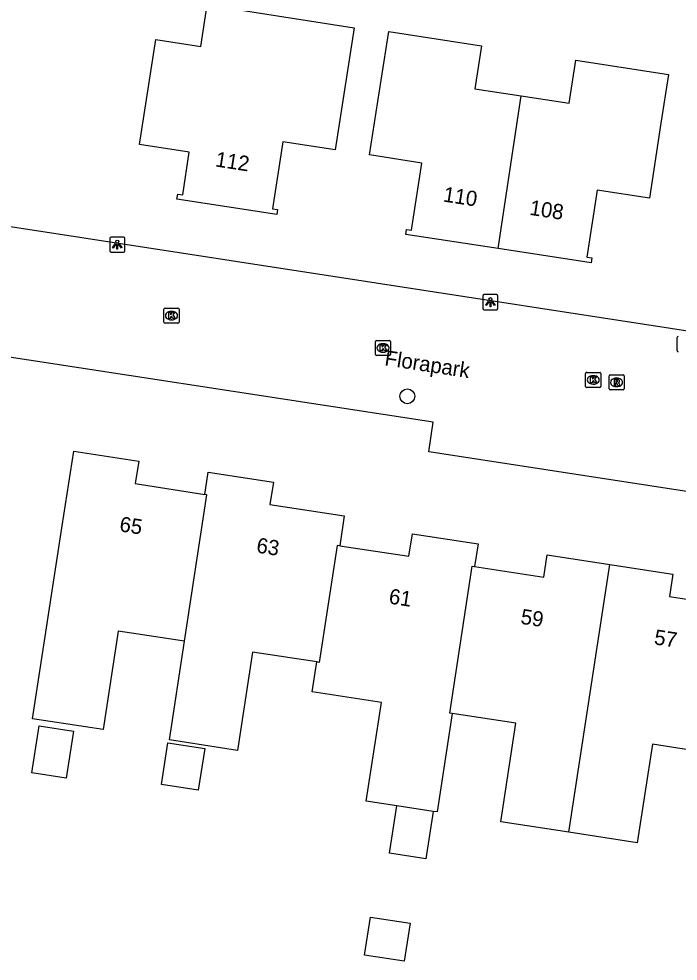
# Model space of a CAD drawing. Extents: x 161486 to 162249, y 379484 to 380829.
# Drawn here: x 161831.1 to 161874.7, y 380679.4 to 380741.6 of the extents above; entities that cross this region are included whole.
import ezdxf

# ---------------------------------------------------------------- set-up
doc = ezdxf.new("R2010")
doc.units = 0
for name, color, linetype in [('IMGEO_Boom', 7, 'Continuous'), ('IMGEO_Brandkraan', 7, 'Continuous'), ('IMGEO_Kolk', 7, 'Continuous'), ('IMGEO_Lichtpunt', 7, 'Continuous'), ('IMGEO_Openbare_ruimte_label', 7, 'Continuous'), ('IMGEO_Pand', 7, 'Continuous'), ('IMGEO_Pand_nummerreeks', 7, 'Continuous'), ('IMGEO_Rijbaan_lokaal_open', 7, 'Continuous'), ('IMGEO_Rioolput', 7, 'Continuous')]:
    doc.layers.add(name, color=color, linetype=linetype)

msp = doc.modelspace()

# ---------------------------------------------------------------- linework, layer by layer
at = {"layer": 'IMGEO_Boom'}
msp.add_circle((161856.794, 380716.676), 0.489, dxfattribs=at)
at = {"layer": 'IMGEO_Brandkraan'}
msp.add_line((161874.599, 380719.698), (161874.599, 380720.55), dxfattribs=at)
msp.add_lwpolyline([(161874.599, 380719.698), (161874.599, 380720.55)], dxfattribs=at)
for centre, start, end in [((161874.676, 380720.548), 91.55205, 178.44795), ((161874.676, 380720.548), 91.55205, 178.44795), ((161874.676, 380719.7), 181.55205, 268.44795), ((161874.676, 380719.7), 181.55205, 268.44795)]:
    msp.add_arc(centre, 0.0765, start, end, dxfattribs=at)
at = {"layer": 'IMGEO_Kolk'}
for p, q in [((161840.723, 380721.58), (161840.723, 380722.432)), ((161840.798, 380722.506), (161841.65, 380722.506)), ((161841.724, 380722.432), (161841.724, 380721.58)), ((161841.234, 380721.726), (161841.209, 380721.726)), ((161841.211, 380722.286), (161841.236, 380722.286)), ((161841.65, 380721.506), (161840.798, 380721.506)), ((161854.687, 380719.443), (161854.687, 380720.295)), ((161854.762, 380720.369), (161855.614, 380720.369)), ((161855.175, 380720.149), (161855.2, 380720.149)), ((161855.688, 380720.295), (161855.688, 380719.443)), ((161855.614, 380719.369), (161854.762, 380719.369)), ((161855.198, 380719.589), (161855.173, 380719.589)), ((161868.567, 380717.333), (161868.567, 380718.185)), ((161868.642, 380718.259), (161869.494, 380718.259)), ((161869.055, 380718.039), (161869.08, 380718.039)), ((161869.568, 380718.185), (161869.568, 380717.333)), ((161869.078, 380717.479), (161869.053, 380717.479)), ((161869.494, 380717.259), (161868.642, 380717.259))]:
    msp.add_line(p, q, dxfattribs=at)
for points in [[(161840.723, 380721.58), (161840.723, 380722.432)], [(161840.798, 380722.506), (161841.65, 380722.506)], [(161841.724, 380722.432), (161841.724, 380721.58)], [(161841.044, 380722.206), (161841.167, 380722.206), (161841.167, 380722.055), (161841.297, 380722.206), (161841.461, 380722.206), (161841.315, 380722.055), (161841.468, 380721.806), (161841.316, 380721.806), (161841.231, 380721.97), (161841.167, 380721.903), (161841.167, 380721.806), (161841.044, 380721.806), (161841.044, 380722.206)], [(161841.65, 380721.506), (161840.798, 380721.506)], [(161854.687, 380719.443), (161854.687, 380720.295)], [(161854.762, 380720.369), (161855.614, 380720.369)], [(161855.008, 380720.069), (161855.131, 380720.069), (161855.131, 380719.918), (161855.261, 380720.069), (161855.425, 380720.069), (161855.279, 380719.918), (161855.432, 380719.669), (161855.28, 380719.669), (161855.195, 380719.833), (161855.131, 380719.766), (161855.131, 380719.669), (161855.008, 380719.669), (161855.008, 380720.069)], [(161855.688, 380720.295), (161855.688, 380719.443)], [(161855.614, 380719.369), (161854.762, 380719.369)], [(161868.567, 380717.333), (161868.567, 380718.185)], [(161868.642, 380718.259), (161869.494, 380718.259)], [(161869.568, 380718.185), (161869.568, 380717.333)], [(161868.888, 380717.959), (161869.011, 380717.959), (161869.011, 380717.808), (161869.141, 380717.959), (161869.305, 380717.959), (161869.159, 380717.808), (161869.312, 380717.559), (161869.16, 380717.559), (161869.075, 380717.723), (161869.011, 380717.656), (161869.011, 380717.559), (161868.888, 380717.559), (161868.888, 380717.959)], [(161869.494, 380717.259), (161868.642, 380717.259)]]:
    msp.add_lwpolyline(points, dxfattribs=at)
for centre, start, end in [((161840.8, 380722.43), 91.55205, 178.44795), ((161840.8, 380722.43), 91.55205, 178.44795), ((161841.648, 380722.43), 1.55205, 88.44795), ((161841.648, 380722.43), 1.55205, 88.44795), ((161840.8, 380721.582), 181.55205, 268.44795), ((161840.8, 380721.582), 181.55205, 268.44795), ((161841.648, 380721.582), 271.55205, 358.44795), ((161841.648, 380721.582), 271.55205, 358.44795), ((161854.764, 380720.293), 91.55205, 178.44795), ((161854.764, 380720.293), 91.55205, 178.44795), ((161855.612, 380720.293), 1.55205, 88.44795), ((161855.612, 380720.293), 1.55205, 88.44795), ((161854.764, 380719.445), 181.55205, 268.44795), ((161854.764, 380719.445), 181.55205, 268.44795), ((161855.612, 380719.445), 271.55205, 358.44795), ((161855.612, 380719.445), 271.55205, 358.44795), ((161868.644, 380718.183), 91.55205, 178.44795), ((161868.644, 380718.183), 91.55205, 178.44795), ((161869.492, 380718.183), 1.55205, 88.44795), ((161869.492, 380718.183), 1.55205, 88.44795), ((161868.644, 380717.335), 181.55205, 268.44795), ((161868.644, 380717.335), 181.55205, 268.44795), ((161869.492, 380717.335), 271.55205, 358.44795), ((161869.492, 380717.335), 271.55205, 358.44795)]:
    msp.add_arc(centre, 0.0765, start, end, dxfattribs=at)
for centre, major_axis, ratio, start_param, end_param in [((161841.21, 380722.006), (-0.387, 0.002), 0.722429, 4.712389, 7.853982), ((161841.235, 380722.006), (-0.39, 0.002), 0.717154, 1.570796, 4.712389), ((161855.174, 380719.869), (-0.387, 0.002), 0.722429, 4.712389, 7.853982), ((161855.199, 380719.869), (-0.39, 0.002), 0.717154, 1.570796, 4.712389), ((161869.054, 380717.759), (-0.387, 0.002), 0.722429, 4.712389, 7.853982), ((161869.079, 380717.759), (-0.39, 0.002), 0.717154, 1.570796, 4.712389)]:
    msp.add_ellipse(centre, major_axis=major_axis, ratio=ratio, start_param=start_param, end_param=end_param, dxfattribs=at)
at = {"layer": 'IMGEO_Lichtpunt'}
for p, q in [((161837.141, 380727.096), (161837.141, 380726.289)), ((161837.141, 380727.096), (161837.141, 380726.289)), ((161838.043, 380727.191), (161837.235, 380727.191)), ((161838.043, 380727.191), (161837.235, 380727.191)), ((161838.137, 380726.289), (161838.137, 380727.096)), ((161838.137, 380726.289), (161838.137, 380727.096)), ((161837.235, 380726.195), (161838.043, 380726.195)), ((161837.235, 380726.195), (161838.043, 380726.195)), ((161861.781, 380723.296), (161861.781, 380722.489)), ((161861.781, 380723.296), (161861.781, 380722.489)), ((161862.683, 380723.391), (161861.875, 380723.391)), ((161862.683, 380723.391), (161861.875, 380723.391)), ((161862.777, 380722.489), (161862.777, 380723.296)), ((161862.777, 380722.489), (161862.777, 380723.296)), ((161861.875, 380722.395), (161862.683, 380722.395)), ((161861.875, 380722.395), (161862.683, 380722.395))]:
    msp.add_line(p, q, dxfattribs=at)
for points in [[(161837.515, 380726.76), (161837.554, 380726.732), (161837.366, 380726.47), (161837.328, 380726.497), (161837.515, 380726.76)], [(161837.617, 380726.712), (161837.664, 380726.712), (161837.664, 380726.39), (161837.617, 380726.39), (161837.617, 380726.712)], [(161837.727, 380726.732), (161837.765, 380726.759), (161837.952, 380726.497), (161837.913, 380726.469), (161837.727, 380726.732)], [(161862.155, 380722.96), (161862.194, 380722.932), (161862.006, 380722.67), (161861.968, 380722.697), (161862.155, 380722.96)], [(161862.257, 380722.912), (161862.304, 380722.912), (161862.304, 380722.59), (161862.257, 380722.59), (161862.257, 380722.912)], [(161862.367, 380722.932), (161862.405, 380722.959), (161862.592, 380722.697), (161862.553, 380722.669), (161862.367, 380722.932)]]:
    msp.add_lwpolyline(points, dxfattribs=at)
for centre in [(161837.64, 380726.894), (161862.28, 380723.094)]:
    msp.add_circle(centre, 0.0994, dxfattribs=at)
for centre, start, end in [((161837.235, 380727.096), 90, 180), ((161837.235, 380727.096), 90, 180), ((161838.043, 380727.096), 0, 90), ((161838.043, 380727.096), 0, 90), ((161837.235, 380726.289), 180, 270), ((161837.235, 380726.289), 180, 270), ((161838.043, 380726.289), 270, 0), ((161838.043, 380726.289), 270, 360), ((161861.875, 380723.296), 90, 180), ((161861.875, 380723.296), 90, 180), ((161862.683, 380723.296), 0, 90), ((161862.683, 380723.296), 0, 90), ((161861.875, 380722.489), 180, 270), ((161861.875, 380722.489), 180, 270), ((161862.683, 380722.489), 270, 0), ((161862.683, 380722.489), 270, 360)]:
    msp.add_arc(centre, 0.0946, start, end, dxfattribs=at)
at = {"layer": 'IMGEO_Pand'}
for points in [[(161852.036, 380732.962), (161848.579, 380733.497), (161847.896, 380729.062), (161848.222, 380729.012), (161848.172, 380728.686), (161841.584, 380729.7), (161841.634, 380730.026), (161841.96, 380729.976), (161842.396, 380732.811), (161839.12, 380733.319), (161840.194, 380740.244), (161843.159, 380739.785), (161843.585, 380742.531), (161853.285, 380741.027), (161852.801, 380737.904), (161852.036, 380732.962)], [(161862.787, 380726.435), (161856.697, 380727.373), (161856.747, 380727.699), (161857.073, 380727.649), (161857.756, 380732.084), (161854.296, 380732.625), (161855.069, 380737.565), (161855.573, 380740.787), (161861.696, 380739.839), (161861.256, 380736.994), (161864.301, 380736.522)], [(161864.301, 380736.522), (161867.468, 380736.032), (161867.908, 380738.877), (161874.031, 380737.929), (161873.538, 380734.717), (161872.78, 380729.774), (161869.323, 380730.304), (161868.649, 380725.866), (161868.976, 380725.816), (161868.926, 380725.49), (161862.787, 380726.435)], [(161862.787, 380726.435), (161864.301, 380736.522)], [(161842.076, 380700.491), (161841.918, 380700.515), (161839.026, 380700.96), (161837.705, 380701.164), (161836.703, 380694.653), (161832.047, 380695.371), (161834.009, 380708.119), (161834.77, 380713.06), (161839.064, 380712.388), (161838.833, 380710.907), (161843.414, 380710.191)], [(161843.414, 380710.191), (161843.645, 380711.672), (161847.95, 380711), (161847.725, 380709.521), (161852.626, 380708.776), (161852.326, 380706.804)], [(161842.076, 380700.491), (161843.549, 380710.17), (161843.414, 380710.191)], [(161852.326, 380706.804), (161856.901, 380706.108), (161857.13, 380707.59), (161861.46, 380706.92), (161861.236, 380705.438)], [(161852.326, 380706.804), (161852.166, 380706.828), (161850.981, 380699.099), (161850.823, 380699.123)], [(161861.236, 380705.438), (161865.808, 380704.732), (161866.03, 380706.21), (161870.174, 380705.572)], [(161867.449, 380687.876), (161870.174, 380705.572)], [(161870.174, 380705.572), (161874.322, 380704.933), (161874.093, 380703.452), (161878.665, 380702.745)], [(161859.761, 380695.725), (161859.594, 380695.751), (161861.076, 380705.463), (161861.236, 380705.438)], [(161850.823, 380699.123), (161846.581, 380699.776), (161845.581, 380693.286), (161841.085, 380693.978), (161842.076, 380700.491)], [(161856.11, 380689.623), (161854.083, 380689.936), (161855.086, 380696.446), (161850.519, 380697.15), (161850.823, 380699.123)], [(161859.761, 380695.725), (161858.758, 380689.215), (161858.494, 380689.256)], [(161867.449, 380687.876), (161862.96, 380688.567), (161863.964, 380695.078), (161859.761, 380695.725)], [(161834.273, 380691.445), (161832.008, 380691.794), (161832.487, 380694.901), (161834.753, 380694.552), (161834.273, 380691.445)], [(161840.563, 380691.029), (161840.987, 380693.773), (161843.413, 380693.399), (161842.99, 380690.654), (161840.563, 380691.029)], [(161877.172, 380693.042), (161872.97, 380693.69), (161871.967, 380687.18), (161867.449, 380687.876)], [(161858.494, 380689.256), (161858.011, 380686.123), (161855.627, 380686.491), (161856.11, 380689.623)], [(161858.494, 380689.256), (161856.11, 380689.623)], [(161856.59, 380679.358), (161853.975, 380679.761), (161854.362, 380682.266), (161856.976, 380681.863), (161856.59, 380679.358)]]:
    msp.add_lwpolyline(points, dxfattribs=at)
at = {"layer": 'IMGEO_Rijbaan_lokaal_open'}
for points in [[(161806.838, 380731.553), (161922.038, 380713.794), (161929.59, 380712.634), (161938.583, 380711.252)], [(161920.72, 380705.36), (161884.401, 380710.951), (161884.124, 380709.027), (161858.224, 380713.01), (161858.506, 380714.977), (161825.187, 380720.083)]]:
    msp.add_lwpolyline(points, dxfattribs=at)
at = {"layer": 'IMGEO_Rioolput'}
for p, q in [((161870.109, 380717.168), (161870.109, 380718.02)), ((161870.184, 380718.094), (161871.036, 380718.094)), ((161871.11, 380718.02), (161871.11, 380717.168)), ((161870.597, 380717.874), (161870.622, 380717.874)), ((161871.036, 380717.094), (161870.184, 380717.094)), ((161870.62, 380717.314), (161870.595, 380717.314))]:
    msp.add_line(p, q, dxfattribs=at)
for points in [[(161870.109, 380717.168), (161870.109, 380718.02)], [(161870.184, 380718.094), (161871.036, 380718.094)], [(161871.11, 380718.02), (161871.11, 380717.168)], [(161870.698, 380717.792), (161870.446, 380717.794), (161870.446, 380717.394)], [(161870.446, 380717.394), (161870.57, 380717.394), (161870.57, 380717.556), (161870.581, 380717.556)], [(161870.624, 380717.713), (161870.57, 380717.713), (161870.57, 380717.632)], [(161870.57, 380717.632), (161870.622, 380717.632)], [(161870.628, 380717.527), (161870.699, 380717.394), (161870.839, 380717.394), (161870.774, 380717.52)], [(161871.036, 380717.094), (161870.184, 380717.094)]]:
    msp.add_lwpolyline(points, dxfattribs=at)
for centre, radius, start, end in [((161870.186, 380718.018), 0.0765, 91.55205, 178.44795), ((161870.186, 380718.018), 0.0765, 91.55205, 178.44795), ((161871.034, 380718.018), 0.0765, 1.55205, 88.44795), ((161871.034, 380718.018), 0.0765, 1.55205, 88.44795), ((161870.58, 380717.503), 0.0533, 26.02933, 88.69889), ((161870.606, 380717.821), 0.19, 274.7715, 282.96867), ((161870.63, 380717.617), 0.0964, 77.00612, 93.18647), ((161870.644, 380717.674), 0.0378, 276.66336, 79.67722), ((161870.697, 380717.682), 0.109, 350.36119, 89.41601), ((161870.695, 380717.682), 0.112, 277.58423, 350.98172), ((161870.679, 380717.467), 0.108, 29.51342, 73.79051), ((161870.186, 380717.17), 0.0765, 181.55205, 268.44795), ((161870.186, 380717.17), 0.0765, 181.55205, 268.44795), ((161871.034, 380717.17), 0.0765, 271.55205, 358.44795), ((161871.034, 380717.17), 0.0765, 271.55205, 358.44795)]:
    msp.add_arc(centre, radius, start, end, dxfattribs=at)
for centre, major_axis, ratio, start_param, end_param in [((161870.596, 380717.594), (-0.387, 0.002), 0.722429, 4.712389, 7.853982), ((161870.621, 380717.594), (-0.39, 0.002), 0.717154, 1.570796, 4.712389)]:
    msp.add_ellipse(centre, major_axis=major_axis, ratio=ratio, start_param=start_param, end_param=end_param, dxfattribs=at)

# ---------------------------------------------------------------- texts
at = {"layer": 'IMGEO_Openbare_ruimte_label'}
msp.add_text('Florapark', height=1, rotation=351.25384, dxfattribs=at).set_placement((161855.25, 380718.733))
at = {"layer": 'IMGEO_Pand_nummerreeks'}
for s, rotation, p in [('112', 351.24992, (161844.076, 380731.866)), ('110', 351.24644, (161859.121, 380729.549)), ('108', 351.24644, (161864.821, 380728.672)), ('65', 351.19364, (161837.744, 380707.761)), ('63', 351.19364, (161846.786, 380706.361)), ('61', 351.2452, (161855.529, 380702.993)), ('59', 351.24639, (161864.231, 380701.652)), ('57', 351.24639, (161873.046, 380700.295))]:
    msp.add_text(s, height=1, rotation=rotation, dxfattribs=at).set_placement(p)

doc.saveas('drawing.dxf')
